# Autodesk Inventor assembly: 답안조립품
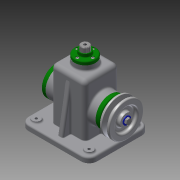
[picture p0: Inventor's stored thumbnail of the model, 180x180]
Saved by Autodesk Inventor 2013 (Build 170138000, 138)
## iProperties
Created: 2016-01
Part Number: 답안조립품
Document SubType Name: Assembly
Designer: Administrator
Author: Administrator
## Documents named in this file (19)
- C:\Users\Administrator\Desktop\460127V1015\답안조립품.iam
- C:\Users\Administrator\Desktop\460127V1015\본체.ipt
- C:\Users\Administrator\Desktop\460127V1015\V-벨트풀리.ipt
- C:\Users\Administrator\Desktop\460127V1015\고정핀.ipt
- C:\Users\Administrator\Desktop\460127V1015\뒤커버.ipt
- C:\Users\Administrator\Desktop\460127V1015\링크.ipt
- C:\Users\Administrator\Desktop\460127V1015\멈춤링 6 x 5.ipt
- C:\Users\Administrator\Desktop\460127V1015\멈춤링 15 x 1.ipt
- C:\Users\Administrator\Desktop\460127V1015\베어링 15 x 35 x 11.ipt
- C:\Users\Administrator\Desktop\460127V1015\볼트 M3 x 8.ipt
- C:\Users\Administrator\Desktop\460127V1015\볼트 M4 x 10.ipt
- C:\Users\Administrator\Desktop\460127V1015\볼트 M6 x 12.ipt
- C:\Users\Administrator\Desktop\460127V1015\상부부시.ipt
- C:\Users\Administrator\Desktop\460127V1015\슬라이드바.ipt
- C:\Users\Administrator\Desktop\460127V1015\앞커버.ipt
- C:\Users\Administrator\Desktop\460127V1015\오일실 15 25 7.ipt
- C:\Users\Administrator\Desktop\460127V1015\와셔.ipt
- C:\Users\Administrator\Desktop\460127V1015\키 5 x 5 x 14.ipt
- C:\Users\Administrator\Desktop\460127V1015\편심축.ipt
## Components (15 placed, 5 different names)
1. V-벨트풀리:1 — 각도:2
2. 고정핀:1
3. ISO 4018 M6 x 12:1
4. ISO 4762 M3 x 8:1
5. ISO 4762 M3 x 8:2
6. ISO 4762 M3 x 8:3
7. ISO 4762 M3 x 8:4
8. ISO 4762 M4 x 10:1
9. ISO 4762 M4 x 10:3
10. ISO 4762 M4 x 10:4
11. ISO 4762 M4 x 10:5
12. ISO 4762 M4 x 10:2
13. ISO 4762 M4 x 10:6
14. ISO 4762 M4 x 10:7
15. ISO 4762 M4 x 10:8
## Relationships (1: Angle 1)
- 각도:2 [Angle]: V-벨트풀리:1
